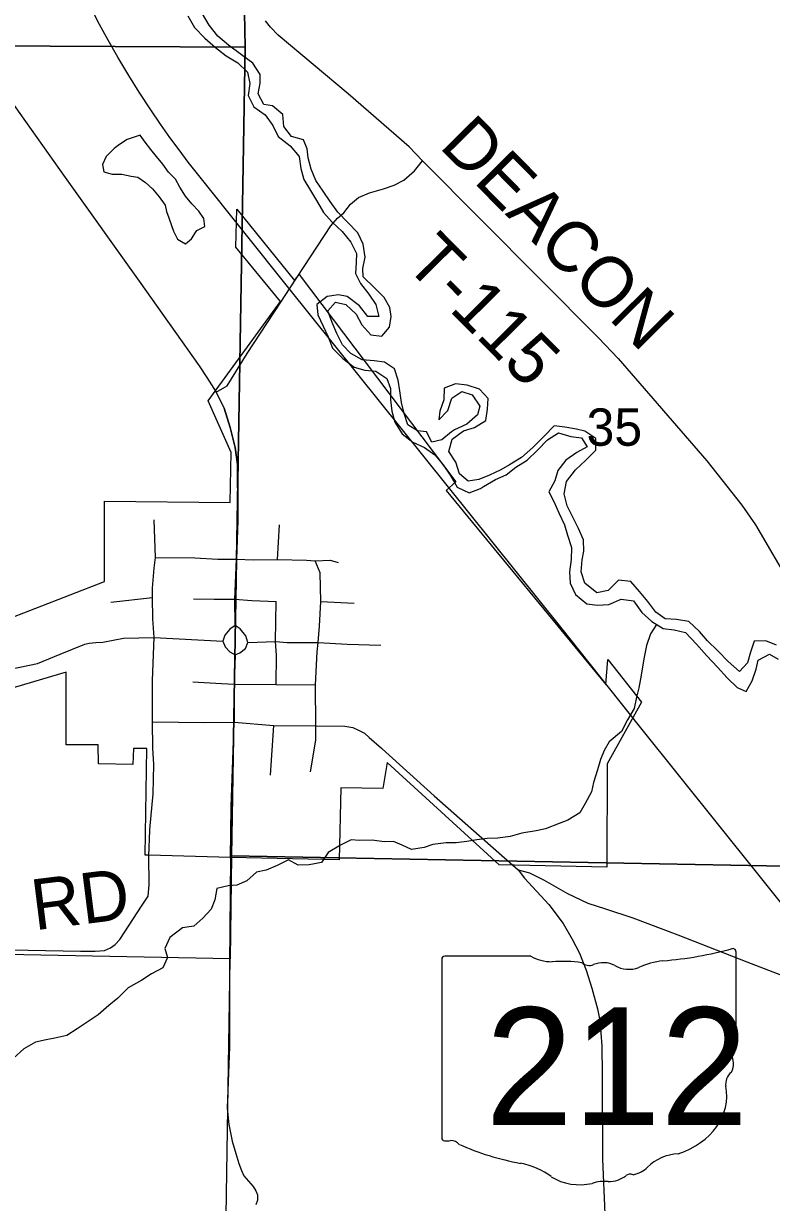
# Model space of a CAD drawing. Extents: x -1.2 to 34, y -8.5 to 22.
# Drawn here: x 5.247 to 6.085, y 18.378 to 19.699 of the extents above; entities that cross this region are included whole.
import ezdxf

# ---------------------------------------------------------------- set-up
doc = ezdxf.new("R2010")
doc.units = 0
for name, color, linetype in [('GM_X_City_Street', 7, 'Continuous'), ('GM_X_Corporation', 7, 'Continuous'), ('GM_X_County_Road', 7, 'Continuous'), ('GM_X_Major_River', 7, 'Continuous'), ('GM_X_Minor_Lake', 7, 'Continuous'), ('GM_X_Minor_River', 7, 'Continuous'), ('GM_X_Rail_Line', 7, 'Continuous'), ('GM_X_Section', 7, 'Continuous'), ('GM_X_Section_Text', 7, 'Continuous'), ('GM_X_State_Location', 7, 'Continuous'), ('GM_X_State_Route', 7, 'Continuous'), ('GM_X_State_Shield', 7, 'Continuous'), ('GM_X_Township_Road', 7, 'Continuous'), ('GM_X_Township_Road_Text', 7, 'Continuous')]:
    doc.layers.add(name, color=color, linetype=linetype)

msp = doc.modelspace()

# ---------------------------------------------------------------- linework, layer by layer
at = {"layer": 'GM_X_City_Street'}
for p, q in [((5.5318, 19.0986), (5.534, 19.1375)), ((5.3452, 19.0508), (5.392, 19.0558)), ((5.5804, 19.0513), (5.6177, 19.0494)), ((5.5242, 18.8569), (5.5279, 18.9124))]:
    msp.add_line(p, q, dxfattribs=at)
for points in [[(5.3939, 19.0886), (5.3951, 19.1008), (5.3937, 19.143)], [(5.3951, 19.1008), (5.4393, 19.1005), (5.4651, 19.0988), (5.4861, 19.0987), (5.5051, 19.0983), (5.5318, 19.0986), (5.5643, 19.0977), (5.574, 19.0969), (5.5907, 19.0977), (5.5999, 19.0952)], [(5.5749, 18.9015), (5.5747, 18.9121), (5.5744, 18.9579), (5.5763, 18.9952), (5.5774, 19.0055), (5.5788, 19.0238), (5.5804, 19.0513), (5.5796, 19.0836), (5.574, 19.0969)], [(5.3889, 18.7962), (5.3926, 18.836), (5.3933, 18.8689), (5.3921, 18.887), (5.3919, 18.9168), (5.3919, 18.963), (5.3938, 19.0111), (5.3924, 19.0321), (5.392, 19.0558), (5.3918, 19.0663), (5.3939, 19.0886)], [(5.4377, 19.0544), (5.461, 19.0542), (5.484, 19.0539), (5.5031, 19.0524), (5.5305, 19.0513)], [(5.5303, 18.9584), (5.5306, 18.9914), (5.5298, 19.0066), (5.5305, 19.0513)], [(5.4985, 19.0056), (5.5298, 19.0066), (5.5426, 19.0055), (5.5774, 19.0055), (5.6099, 19.0035), (5.6477, 19.0027)], [(5.4369, 18.9614), (5.4693, 18.9595), (5.4832, 18.959), (5.5303, 18.9584), (5.5744, 18.9579)], [(5.3919, 18.9168), (5.45, 18.9158), (5.4834, 18.9163)], [(5.4793, 18.7639), (5.4801, 18.8214), (5.4834, 18.9163)], [(5.569, 18.8608), (5.575, 18.8962), (5.5749, 18.9015)], [(5.3878, 18.7665), (5.3888, 18.7948), (5.3889, 18.7962)]]:
    msp.add_lwpolyline(points, dxfattribs=at)
at = {"layer": 'GM_X_Corporation'}
msp.add_lwpolyline([(5.184, 19.014), (5.338, 19.0737), (5.338, 19.1637), (5.4787, 19.1624), (5.48, 19.2184), (5.4544, 19.2762), (5.5354, 19.3874), (5.4853, 19.4485), (5.4863, 19.491), (5.5508, 19.4109), (5.556, 19.4178), (5.7317, 19.1854), (5.7208, 19.1758), (5.8996, 18.9586), (5.9019, 18.9863), (5.9398, 18.9386), (5.9011, 18.8697), (5.9009, 18.7539), (5.7801, 18.7565), (5.6546, 18.8712), (5.65, 18.842), (5.603, 18.8428), (5.6008, 18.762), (5.4791, 18.7645), (5.3876, 18.7671), (5.3836, 18.7672), (5.3855, 18.8867), (5.3707, 18.8868), (5.3697, 18.8687), (5.3315, 18.8697), (5.3311, 18.8907), (5.2953, 18.8909), (5.2952, 18.9721), (5.2078, 18.9465)], dxfattribs=at)
at = {"layer": 'GM_X_County_Road'}
for p, q in [((5.484, 19.0539), (5.4861, 19.0987)), ((5.4845, 19.0246), (5.484, 19.0539))]:
    msp.add_line(p, q, dxfattribs=at)
for points in [[(5.5462, 19.403), (5.5915, 19.4723), (5.5992, 19.4807), (5.6061, 19.4868), (5.6101, 19.4916), (5.6136, 19.4966), (5.6228, 19.5042), (5.6349, 19.5093), (5.6508, 19.5138), (5.6626, 19.5179), (5.6734, 19.5236), (5.6854, 19.5338), (5.6943, 19.5452), (5.6794, 19.5609), (5.611, 19.6201), (5.5328, 19.6858), (5.5242, 19.6947), (5.5184, 19.7019)], [(5.4633, 19.2858), (5.4755, 19.2929), (5.498, 19.3292), (5.5357, 19.3869), (5.5462, 19.403)], [(5.4873, 19.1518), (5.4872, 19.2051), (5.4843, 19.2239), (5.4788, 19.2465), (5.4722, 19.268), (5.4633, 19.2858)], [(5.4861, 19.0987), (5.4873, 19.1422), (5.4873, 19.1518)], [(5.4985, 19.0056), (5.4964, 19.0129), (5.49, 19.0208), (5.4845, 19.0246)], [(5.1977, 18.9684), (5.1996, 18.9691), (5.2629, 18.982), (5.2885, 18.9924), (5.3162, 19.0036), (5.3209, 19.0046), (5.3283, 19.0054), (5.3364, 19.0057), (5.3595, 19.0102), (5.3938, 19.0111), (5.4707, 19.007)], [(5.4707, 19.007), (5.4731, 19.0007), (5.4784, 18.995), (5.4846, 18.9916)], [(5.4846, 18.9916), (5.4898, 18.9941), (5.4959, 18.9989), (5.4985, 19.0056)]]:
    msp.add_lwpolyline(points, dxfattribs=at)
at = {"layer": 'GM_X_Major_River'}
for points in [[(5.4314, 19.7075), (5.4388, 19.6943), (5.4504, 19.6824), (5.4624, 19.6719), (5.4743, 19.6626), (5.4874, 19.6549), (5.4982, 19.6444), (5.501, 19.6316), (5.499, 19.6183), (5.5053, 19.6055), (5.518, 19.5966), (5.5265, 19.5846), (5.5328, 19.5722), (5.5459, 19.5618), (5.556, 19.5498), (5.5581, 19.5366), (5.5614, 19.5241), (5.5688, 19.5117), (5.5766, 19.4989), (5.5833, 19.4873), (5.593, 19.4764), (5.6045, 19.466), (5.6139, 19.454), (5.6205, 19.4412), (5.6199, 19.4313), (5.6194, 19.4188), (5.6249, 19.4075), (5.6342, 19.3959), (5.642, 19.3843), (5.6453, 19.3707), (5.6331, 19.3708), (5.6238, 19.3825), (5.6099, 19.3932), (5.6004, 19.395), (5.5875, 19.3932), (5.5759, 19.3843), (5.5772, 19.3726), (5.5831, 19.3598), (5.5886, 19.3481), (5.5934, 19.3353), (5.605, 19.3237), (5.6177, 19.3141), (5.6296, 19.3105), (5.6421, 19.3095), (5.6544, 19.3014), (5.6584, 19.2901), (5.6586, 19.2775), (5.66, 19.2647), (5.6632, 19.2522), (5.6714, 19.2394), (5.6833, 19.2298), (5.6964, 19.2239), (5.7083, 19.2158), (5.7176, 19.2045), (5.7262, 19.1918), (5.7332, 19.1797), (5.7466, 19.1731), (5.7591, 19.1779)], [(5.614, 19.3292), (5.6048, 19.3389), (5.5985, 19.3517), (5.5933, 19.3641), (5.5882, 19.3769), (5.5967, 19.3866), (5.6086, 19.3841), (5.6201, 19.3733), (5.6264, 19.3613), (5.6365, 19.35), (5.6487, 19.3487), (5.6573, 19.3587), (5.6593, 19.3709), (5.6577, 19.3807), (5.6514, 19.392), (5.6406, 19.4028), (5.6278, 19.4152), (5.6273, 19.4246), (5.6301, 19.4372), (5.628, 19.4516), (5.6217, 19.4644), (5.6105, 19.476), (5.5996, 19.4875), (5.5907, 19.4995), (5.5829, 19.5112), (5.5747, 19.5232), (5.5695, 19.5356), (5.5663, 19.5484), (5.565, 19.5587), (5.561, 19.5685), (5.5477, 19.5724), (5.5391, 19.5837), (5.5377, 19.5969), (5.5262, 19.6066), (5.5166, 19.6083), (5.5104, 19.62), (5.5124, 19.6322), (5.5123, 19.642), (5.5041, 19.6544), (5.4914, 19.6637), (5.4771, 19.6748), (5.4652, 19.6849), (5.4555, 19.6972), (5.4477, 19.7096)], [(5.7269, 19.2415), (5.716, 19.2326), (5.7046, 19.2301), (5.6987, 19.2414), (5.6888, 19.2428), (5.6777, 19.2494), (5.6737, 19.2619), (5.6708, 19.2743), (5.6691, 19.2876), (5.667, 19.2993), (5.663, 19.3121), (5.6518, 19.3196), (5.64, 19.3209), (5.6267, 19.3222), (5.614, 19.3292)], [(6.0908, 19.0024), (6.0789, 19.0075), (6.066, 19.0069), (6.0617, 18.9947), (6.0584, 18.9829), (6.0495, 18.9732), (6.0367, 18.9844), (6.0251, 18.9963), (6.0136, 19.0072), (6.0046, 19.018), (5.9927, 19.0292), (5.9789, 19.0313), (5.966, 19.0322), (5.9556, 19.0396), (5.9467, 19.0516), (5.9374, 19.0628), (5.9277, 19.0737), (5.914, 19.0753), (5.9024, 19.0638), (5.8895, 19.0613), (5.876, 19.0721), (5.872, 19.0845), (5.8733, 19.0982), (5.875, 19.1077), (5.8745, 19.1206), (5.8689, 19.1334), (5.8626, 19.1458), (5.8563, 19.1586), (5.8531, 19.1722), (5.8555, 19.1859), (5.8656, 19.199), (5.8768, 19.2094), (5.8884, 19.221), (5.8885, 19.2339), (5.8762, 19.2424), (5.8667, 19.2446), (5.8537, 19.2466), (5.8419, 19.2483), (5.8307, 19.2368), (5.818, 19.224), (5.8053, 19.2128), (5.7917, 19.2046), (5.7819, 19.1991), (5.7695, 19.1929), (5.7574, 19.1881), (5.7456, 19.1864), (5.7356, 19.1946), (5.7316, 19.2074), (5.7238, 19.2194), (5.7274, 19.2332), (5.7402, 19.2425), (5.7526, 19.2465), (5.7654, 19.2543), (5.7671, 19.2668), (5.7677, 19.279), (5.758, 19.2894), (5.7442, 19.2938), (5.7313, 19.2951), (5.7185, 19.2903), (5.7183, 19.2774), (5.7136, 19.2648), (5.7126, 19.2549), (5.7227, 19.2653), (5.727, 19.2791), (5.7383, 19.2868), (5.7501, 19.2829), (5.7587, 19.2701), (5.7558, 19.2606), (5.7438, 19.2501), (5.7303, 19.2438), (5.7269, 19.2415)], [(5.7591, 19.1779), (5.7625, 19.1802), (5.776, 19.188), (5.7881, 19.1932), (5.799, 19.2021), (5.8114, 19.2099), (5.823, 19.2211), (5.8342, 19.2326), (5.8466, 19.2404), (5.8604, 19.2361), (5.8726, 19.2348), (5.8788, 19.2247), (5.8671, 19.2184), (5.8547, 19.2098), (5.8458, 19.1983), (5.8426, 19.1865), (5.8359, 19.1742), (5.8418, 19.1629), (5.847, 19.1509), (5.8533, 19.1373), (5.8569, 19.1256), (5.8613, 19.112), (5.8608, 19.0984), (5.8591, 19.0847), (5.8597, 19.0718), (5.8656, 19.0594), (5.8783, 19.0489), (5.8905, 19.0473), (5.903, 19.0482), (5.917, 19.0541), (5.9307, 19.0521), (5.94, 19.0393), (5.9512, 19.0289), (5.9639, 19.0211), (5.9761, 19.0198), (5.9891, 19.0166), (6.0014, 19.0035), (6.0127, 18.9904), (6.0247, 18.9777), (6.0355, 18.9658), (6.0467, 18.955), (6.0567, 18.9506), (6.0637, 18.9624), (6.068, 18.9758), (6.0705, 18.9857), (6.083, 18.9924), (6.0926, 18.9868)]]:
    msp.add_lwpolyline(points, dxfattribs=at)
at = {"layer": 'GM_X_Minor_Lake'}
for points in [[(5.378, 19.5737), (5.3636, 19.5691), (5.3549, 19.5633), (5.3489, 19.5591), (5.3398, 19.5499), (5.3357, 19.5411), (5.3373, 19.5328), (5.3465, 19.5302), (5.3575, 19.5303), (5.3678, 19.5281), (5.3754, 19.5267), (5.3842, 19.5207), (5.3918, 19.5139), (5.3995, 19.5049), (5.406, 19.4954), (5.4076, 19.4882), (5.4103, 19.4811), (5.4131, 19.4727), (5.4154, 19.4663), (5.42, 19.4572), (5.4288, 19.452), (5.4356, 19.4577), (5.4401, 19.4647)], [(5.4401, 19.4647), (5.4416, 19.4669), (5.4503, 19.4715), (5.4495, 19.4806), (5.4437, 19.4889), (5.436, 19.4968), (5.4287, 19.5055), (5.4226, 19.5157), (5.4176, 19.5244), (5.4099, 19.5323), (5.4033, 19.5413), (5.3964, 19.55), (5.3899, 19.5579), (5.3838, 19.5662), (5.378, 19.5737)]]:
    msp.add_lwpolyline(points, dxfattribs=at)
at = {"layer": 'GM_X_Minor_River'}
msp.add_lwpolyline([(5.9565, 19.0257), (5.9499, 19.0151), (5.9451, 19.0021), (5.9422, 18.9873), (5.9408, 18.9778), (5.9386, 18.9649), (5.9368, 18.9546), (5.9342, 18.9444), (5.9313, 18.9314), (5.9238, 18.9188), (5.9171, 18.9059), (5.9035, 18.8944), (5.8979, 18.8845), (5.8938, 18.8746), (5.8905, 18.8628), (5.886, 18.8487), (5.8835, 18.8384), (5.8764, 18.8251), (5.8704, 18.8148), (5.8572, 18.8063), (5.8473, 18.8028), (5.8322, 18.7966), (5.8215, 18.7946), (5.8056, 18.7918), (5.7927, 18.7883), (5.7787, 18.7863), (5.7669, 18.7858), (5.7552, 18.7846), (5.7438, 18.7826), (5.732, 18.781), (5.721, 18.7809), (5.7058, 18.7792), (5.696, 18.7757), (5.682, 18.7737), (5.6717, 18.7786), (5.6617, 18.7826), (5.6515, 18.7822), (5.6378, 18.784), (5.6238, 18.7838), (5.6143, 18.7845), (5.6025, 18.7783), (5.5885, 18.7703), (5.581, 18.7592), (5.5674, 18.7564), (5.5549, 18.7559), (5.5442, 18.7619), (5.5317, 18.7557), (5.5192, 18.7503), (5.5082, 18.7483), (5.4977, 18.7384), (5.4863, 18.7337), (5.4768, 18.7329), (5.4639, 18.7301), (5.4618, 18.7172), (5.4577, 18.7069), (5.4483, 18.6966), (5.4381, 18.6878), (5.4256, 18.6857), (5.4112, 18.675), (5.4056, 18.6628), (5.4088, 18.6526), (5.4035, 18.6411), (5.3907, 18.6342), (5.3801, 18.6273), (5.3646, 18.6188), (5.3529, 18.6069), (5.3428, 18.5989), (5.3311, 18.5885), (5.3175, 18.5793), (5.3073, 18.5728), (5.2959, 18.5651), (5.2823, 18.5623), (5.2728, 18.5603), (5.2607, 18.5576), (5.2478, 18.5502), (5.2362, 18.5399)], dxfattribs=at)
at = {"layer": 'GM_X_Rail_Line'}
msp.add_lwpolyline([(6.1831, 18.605), (6.07, 18.7464), (5.9375, 18.9118), (5.8492, 19.0228), (5.5446, 19.4026), (5.4439, 19.5286), (5.4319, 19.5436), (5.4217, 19.5576), (5.4114, 19.5713), (5.4007, 19.5863), (5.3899, 19.6023), (5.3768, 19.622), (5.3653, 19.6407), (5.3531, 19.6611), (5.3422, 19.6804), (5.3325, 19.6978), (5.3223, 19.7178)], dxfattribs=at)
at = {"layer": 'GM_X_Section'}
for points in [[(5.5138, 20.6632), (5.4939, 19.7699), (5.4956, 19.6725), (4.4756, 19.6778), (4.4978, 20.6761)], [(5.4939, 19.7699), (6.3436, 19.7459), (6.3194, 18.751), (5.4804, 18.7665), (5.4956, 19.6725)], [(4.4756, 19.6778), (5.4956, 19.6725), (5.4804, 18.7665), (5.479, 18.6512), (4.4573, 18.6708)], [(5.4804, 18.7665), (6.3194, 18.751), (6.3024, 17.731), (5.4646, 17.7402), (5.479, 18.6512)]]:
    msp.add_lwpolyline(points, close=True, dxfattribs=at)
at = {"layer": 'GM_X_State_Route'}
for p, q in [((5.4526, 19.3023), (5.4633, 19.2858)), ((5.4861, 19.0987), (5.484, 19.0539)), ((5.484, 19.0539), (5.4845, 19.0246)), ((5.786, 18.7644), (5.8014, 18.7508))]:
    msp.add_line(p, q, dxfattribs=at)
for points in [[(5.1434, 19.764), (5.1765, 19.6954), (5.1836, 19.6849), (5.2048, 19.6519), (5.2942, 19.5266), (5.3768, 19.4104), (5.444, 19.3156), (5.4526, 19.3023)], [(5.4633, 19.2858), (5.4722, 19.268), (5.4788, 19.2465), (5.4843, 19.2239), (5.4872, 19.2051), (5.4873, 19.1518)], [(5.4873, 19.1518), (5.4873, 19.1422), (5.4861, 19.0987)], [(5.4845, 19.0246), (5.4786, 19.0206), (5.4729, 19.0138), (5.4707, 19.007)], [(5.4985, 19.0056), (5.4964, 19.0129), (5.49, 19.0208), (5.4845, 19.0246)], [(5.4707, 19.007), (5.4731, 19.0007), (5.4784, 18.995), (5.4846, 18.9916)], [(5.4846, 18.9916), (5.4898, 18.9941), (5.4959, 18.9989), (5.4985, 19.0056)], [(5.4846, 18.9916), (5.4832, 18.959), (5.4834, 18.9163), (5.5279, 18.9124), (5.5747, 18.9121), (5.6073, 18.9117), (5.6163, 18.9102), (5.6226, 18.9074), (5.6293, 18.9039), (5.6344, 18.8992), (5.6483, 18.8871)], [(5.6483, 18.8871), (5.649, 18.8864), (5.7074, 18.8337), (5.786, 18.7644)], [(5.8014, 18.7508), (5.8143, 18.7476), (5.8306, 18.7393), (5.8569, 18.7242), (5.8797, 18.7134), (5.8992, 18.7071), (5.93, 18.6969), (5.9805, 18.6779), (6.0578, 18.6479), (6.0819, 18.6384), (6.0964, 18.6327)], [(5.8014, 18.7508), (5.8084, 18.7414), (5.836, 18.712), (5.8519, 18.6909), (5.8621, 18.6731), (5.8702, 18.6574), (5.8776, 18.6384), (5.884, 18.6181), (5.8905, 18.595), (5.8929, 18.582), (5.8953, 18.5536), (5.8956, 18.5212), (5.8959, 18.4268), (5.8984, 18.3655)]]:
    msp.add_lwpolyline(points, dxfattribs=at)
at = {"layer": 'GM_X_State_Shield'}
for p, q in [((5.7159, 18.6508), (5.7159, 18.4507)), ((5.8157, 18.6542), (5.7192, 18.6542)), ((6.0455, 18.5545), (6.0455, 18.6592)), ((6.0455, 18.5545), (6.0455, 18.5545))]:
    msp.add_line(p, q, dxfattribs=at)
for centre, major_axis, start_param, end_param in [((5.9281, 18.9271), (0.3495, 0), 4.814394, 5.042369), ((6.0418, 18.6596), (0.00367, 0), 6.141152, 7.989035), ((5.7197, 18.6512), (0.00382, 0), 1.712693, 3.28349), ((5.8387, 18.6775), (0.037, 0), 4.042523, 4.731795), ((5.8509, 18.5419), (0.133, 0), 1.404758, 1.657858), ((5.8968, 18.6291), (0.0222, 0), 0.950623, 2.079405), ((5.9727, 18.5931), (0.0703, 0), 1.699011, 2.107814), ((5.8811, 18.6523), (0.0107, 0), 3.836095, 5.185415), ((5.9255, 18.6608), (0.0267, 0), 4.081561, 5.145723), ((6.0447, 18.5468), (0.00568, 0), 1.883978, 3.671073), ((6.0085, 18.5336), (0.0341, 0), 5.934695, 6.695948), ((6.0416, 18.5541), (0.00393, 0), 5.05454, 6.418171), ((6.0586, 18.5107), (0.0248, 0), 2.387724, 3.262537), ((5.9477, 18.4974), (0.0874, 0), 5.101752, 6.440018), ((5.7197, 18.4502), (0.00385, 0), 3.00124, 4.508301), ((5.7203, 18.4707), (0.0294, 0), 4.665946, 4.897461), ((5.7263, 18.4391), (0.0106, 0), 0.519207, 1.627899), ((5.8602, 18.6189), (0.2524, 0), 4.195997, 4.488961), ((5.9845, 18.3945), (0.0479, 0), 1.647645, 2.488434), ((5.7849, 18.3608), (0.079, 0), 0.823519, 1.323587), ((5.9271, 18.4038), (0.00752, 0), 1.147584, 2.315152), ((5.9239, 18.4313), (0.0282, 0), 4.937069, 5.64225), ((5.8703, 18.4381), (0.0501, 0), 4.026481, 4.996735), ((5.8993, 18.3689), (0.0412, 0), 1.495662, 1.94098), ((5.9029, 18.4231), (0.0267, 0), 4.691044, 5.507374)]:
    msp.add_ellipse(centre, major_axis=major_axis, ratio=0.8, start_param=start_param, end_param=end_param, dxfattribs=at)
at = {"layer": 'GM_X_Township_Road'}
for points in [[(5.6943, 19.5452), (5.8914, 19.3468), (5.9134, 19.3236), (6.0128, 19.2091), (6.0519, 19.1592), (6.0673, 19.1373), (6.1087, 19.0662)], [(4.9631, 18.6293), (5.0266, 18.6353), (5.0346, 18.6368), (5.0372, 18.6374), (5.0497, 18.643), (5.0878, 18.6619), (5.0905, 18.6627), (5.0938, 18.6634), (5.0973, 18.6639), (5.1156, 18.6635), (5.3113, 18.6596), (5.3277, 18.6599), (5.3381, 18.6605), (5.345, 18.6633), (5.3499, 18.6671), (5.3551, 18.6728), (5.3804, 18.7111), (5.3871, 18.7213), (5.3882, 18.7342), (5.3878, 18.7665)], [(5.4793, 18.7639), (5.4782, 18.6451), (5.4783, 18.5525), (5.4754, 18.4839), (5.4772, 18.4656), (5.481, 18.447), (5.4852, 18.4332), (5.4886, 18.4217), (5.4914, 18.4141), (5.494, 18.4082), (5.4994, 18.4021), (5.5048, 18.3959), (5.5077, 18.3914), (5.5094, 18.3867), (5.5096, 18.3808), (5.5077, 18.3755)]]:
    msp.add_lwpolyline(points, dxfattribs=at)

# ---------------------------------------------------------------- texts
at = {"layer": 'GM_X_Section_Text'}
msp.add_text('35', height=0.04186, rotation=0, dxfattribs=at).set_placement((5.8781, 19.2259))
at = {"layer": 'GM_X_State_Location'}
for s in ['s', 'r']:
    msp.add_text(s, height=0.000189, dxfattribs=at).set_placement((5.877, 18.5374))
msp.add_text('212', height=0.000189, rotation=0, dxfattribs=at).set_placement((5.8101, 18.5236))
at = {"layer": 'GM_X_State_Shield'}
msp.add_text('212', height=0.13184, dxfattribs=at).set_placement((5.7649, 18.4648))
at = {"layer": 'GM_X_Township_Road_Text'}
for s, rotation, p in [('DEACON', 314.6496, (5.7119, 19.5607)), ('T-115', 314.8019, (5.6727, 19.4289)), ('RD', 7.1885, (5.2599, 18.683))]:
    msp.add_text(s, height=0.05682, rotation=rotation, dxfattribs=at).set_placement(p)

doc.saveas('drawing.dxf')
